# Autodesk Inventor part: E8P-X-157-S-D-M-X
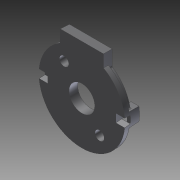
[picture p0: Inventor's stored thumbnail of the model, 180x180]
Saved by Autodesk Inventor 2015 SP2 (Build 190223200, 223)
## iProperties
Created: 2012-07
Part Number: E8P-X-157-S-D-M-X
Material: Allgemein
Document SubType Name: Modeling
Designer: rYan
Density: 1 g/cm^3
Mass: 1.6157 g
Surface Area: 16.7843 cm^2
Volume: 1.6157 cm^3
Appearance: Vorgabe
Author: rYan
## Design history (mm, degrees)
node "E8P-X-157-S-D-M-X1"
node "E8P-X-157-S-D-M-X"
node "Basis1"
